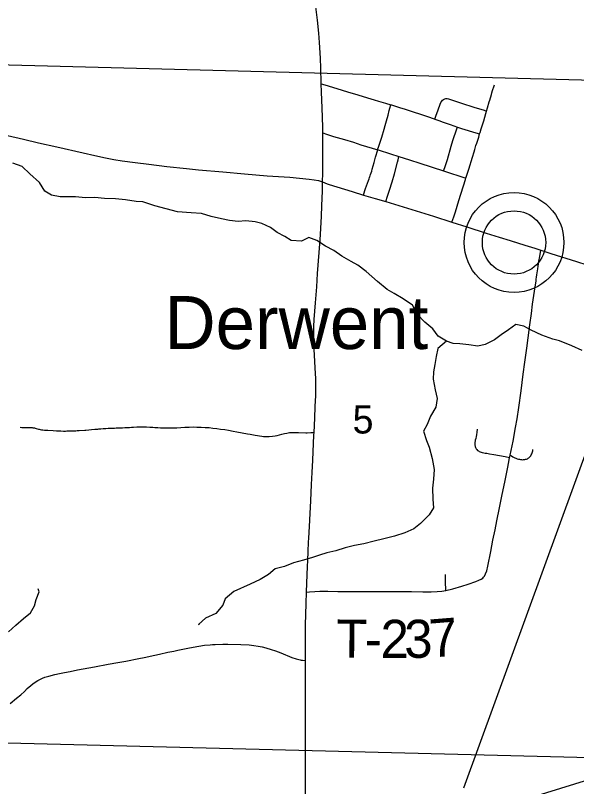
# Model space of a CAD drawing. Extents: x 0 to 34, y 0 to 22.
# Drawn here: x 28.206 to 29.042, y 19.567 to 20.718 of the extents above; entities that cross this region are included whole.
import ezdxf

# ---------------------------------------------------------------- set-up
doc = ezdxf.new("R2010")
doc.units = 0
for name, color, linetype in [('GM_X_Corporation', 7, 'Continuous'), ('GM_X_Minor_River', 7, 'Continuous'), ('GM_X_Rail_Line', 7, 'Continuous'), ('GM_X_Section_Text', 7, 'Continuous'), ('GM_X_State_Route', 7, 'Continuous'), ('GM_X_Township_Road', 7, 'Continuous'), ('GM_X_Township_Road_Text', 7, 'Continuous'), ('GM_X_Unincorporated', 7, 'Continuous'), ('GM_X_Unincorporated_Location', 7, 'Continuous'), ('GM_X_Unincorporated_Text', 7, 'Continuous')]:
    doc.layers.add(name, color=color, linetype=linetype)

msp = doc.modelspace()

# ---------------------------------------------------------------- linework, layer by layer
at = {"layer": 'GM_X_Corporation'}
for points in [[(29.1717, 20.9), (28.1474, 20.9), (28.1412, 20.646), (28.1583, 20.645), (29.1631, 20.6187)], [(28.1583, 20.645), (29.1631, 20.6187), (29.1414, 19.6082), (28.1343, 19.6338)]]:
    msp.add_lwpolyline(points, close=True, dxfattribs=at)
at = {"layer": 'GM_X_Minor_River'}
for points in [[(29.0505, 20.2181), (29.0349, 20.2248), (29.0167, 20.2322), (29.0065, 20.2347), (28.9902, 20.241), (28.9742, 20.248), (28.9636, 20.254), (28.9515, 20.2565), (28.9406, 20.2488), (28.9297, 20.2415), (28.9199, 20.2338), (28.906, 20.2268), (28.895, 20.2244), (28.8814, 20.2262), (28.8682, 20.228), (28.8583, 20.2282), (28.8481, 20.2319), (28.8356, 20.2394), (28.8279, 20.2503), (28.8157, 20.26), (28.8046, 20.272), (28.7977, 20.2856), (28.7837, 20.2949), (28.7704, 20.3027), (28.7597, 20.309), (28.7452, 20.321), (28.7285, 20.3356), (28.7159, 20.3454), (28.706, 20.3506), (28.6924, 20.3584), (28.6802, 20.367), (28.6677, 20.3733), (28.6547, 20.3818), (28.643, 20.3866), (28.6321, 20.3812), (28.6169, 20.3818), (28.6074, 20.3878), (28.5957, 20.3937), (28.5861, 20.4012), (28.5729, 20.4075), (28.563, 20.4097), (28.549, 20.4111), (28.5377, 20.4102), (28.5248, 20.4116), (28.5127, 20.4145), (28.4975, 20.4177), (28.4831, 20.4221), (28.4676, 20.4231), (28.4472, 20.4248), (28.4135, 20.4335), (28.3957, 20.4394), (28.3854, 20.44), (28.3699, 20.4425), (28.3548, 20.4439), (28.3385, 20.4448), (28.3241, 20.4462), (28.3102, 20.4457), (28.2954, 20.447), (28.2833, 20.4469), (28.2724, 20.4472), (28.2595, 20.4497), (28.2496, 20.4553), (28.2415, 20.4685), (28.2271, 20.4816), (28.2156, 20.4921), (28.202, 20.4972)], [(28.8481, 20.2319), (28.8353, 20.2208), (28.8328, 20.209), (28.8306, 20.1969), (28.8288, 20.1859), (28.8282, 20.1752), (28.8314, 20.159), (28.8345, 20.1461), (28.8323, 20.1336), (28.8245, 20.1199), (28.8193, 20.1073), (28.8141, 20.0978), (28.8184, 20.0838), (28.8223, 20.0736), (28.827, 20.0566), (28.8297, 20.0403), (28.8287, 20.0259), (28.8273, 20.0127), (28.8279, 19.9964), (28.8287, 19.9831), (28.8224, 19.9728), (28.8093, 19.9598), (28.7995, 19.9517), (28.786, 19.9459), (28.7705, 19.9412), (28.755, 19.9369), (28.7403, 19.9333), (28.7249, 19.9297), (28.7109, 19.9269), (28.697, 19.9234), (28.6834, 19.9191), (28.6698, 19.9159), (28.6589, 19.9124), (28.6487, 19.9092), (28.6351, 19.9053), (28.62, 19.901), (28.6068, 19.8959), (28.5929, 19.892), (28.5831, 19.8839), (28.5703, 19.8762), (28.5557, 19.8692), (28.5312, 19.8584), (28.5184, 19.8476), (28.5147, 19.8381), (28.5046, 19.8255), (28.4892, 19.8189), (28.4787, 19.8093), (28.4798, 19.8097)], [(28.1953, 19.7984), (28.2062, 19.808), (28.2178, 19.8183), (28.2279, 19.8267), (28.2339, 19.837), (28.2368, 19.8465), (28.2409, 19.858), (28.2397, 19.8625)]]:
    msp.add_lwpolyline(points, dxfattribs=at)
at = {"layer": 'GM_X_Rail_Line'}
for points in [[(28.8741, 19.5654), (29.0627, 20.0841), (29.0894, 20.1621), (29.1142, 20.2409), (29.1356, 20.3363), (29.1474, 20.4062), (29.1551, 20.4639), (29.161, 20.4964)], [(28.8515, 19.5134), (29.4007, 19.6833), (29.491, 19.707), (29.5813, 19.7244), (29.9149, 19.7778), (30.0206, 19.7932), (30.1151, 19.8044), (30.1859, 19.8065), (30.2475, 19.8096), (30.2867, 19.817), (30.3167, 19.8284)]]:
    msp.add_lwpolyline(points, dxfattribs=at)
at = {"layer": 'GM_X_State_Route'}
for points in [[(28.6394, 19.8575), (28.6398, 19.8711), (28.6409, 19.8959), (28.6414, 19.9046), (28.6422, 19.9182), (28.6427, 19.9318), (28.643, 19.938), (28.6438, 19.9553), (28.6448, 19.975), (28.6458, 19.9939), (28.6469, 20.0179), (28.6478, 20.0359), (28.6488, 20.0545), (28.6506, 20.0917), (28.6508, 20.0956), (28.6517, 20.1171), (28.6526, 20.1345), (28.6532, 20.1506), (28.6534, 20.1624), (28.6533, 20.1754), (28.6526, 20.1921), (28.6515, 20.2107), (28.6505, 20.2274), (28.6502, 20.2393), (28.6503, 20.2536), (28.6508, 20.2642), (28.6529, 20.289), (28.6548, 20.3131), (28.6561, 20.3329), (28.6598, 20.383), (28.6609, 20.3997), (28.6617, 20.4183), (28.6623, 20.4338), (28.6633, 20.4561), (28.6636, 20.4694), (28.664, 20.4822), (28.664, 20.4939), (28.6638, 20.5281), (28.6637, 20.5427), (28.6637, 20.5504), (28.6634, 20.5659), (28.6629, 20.5795), (28.6621, 20.6037), (28.6616, 20.6157), (28.6616, 20.6173), (28.6609, 20.639), (28.6602, 20.6539), (28.6587, 20.6775), (28.6577, 20.6911), (28.6557, 20.7108), (28.6534, 20.7305)], [(28.194, 20.5387), (28.2175, 20.533), (28.2399, 20.5277), (28.2672, 20.5216), (28.3066, 20.5126), (28.3241, 20.5087), (28.3399, 20.5055), (28.3521, 20.503), (28.365, 20.501), (28.384, 20.4983), (28.4043, 20.4956), (28.4314, 20.4923), (28.4605, 20.4893), (28.4784, 20.4875), (28.5149, 20.4842), (28.5471, 20.4813), (28.5811, 20.4786), (28.6146, 20.4763), (28.6437, 20.4735), (28.6511, 20.4724), (28.6573, 20.4713), (28.6636, 20.4694)], [(28.6636, 20.4694), (28.6666, 20.4682), (28.6704, 20.4667), (28.6734, 20.4656), (28.7074, 20.4551), (28.7247, 20.4498), (28.7419, 20.4447), (28.7578, 20.4399), (28.7966, 20.4282), (28.8286, 20.4182), (28.8562, 20.4093), (28.8783, 20.4022), (28.9073, 20.3931), (28.9269, 20.3869), (28.9429, 20.3818), (28.9648, 20.3749), (28.9796, 20.3703), (28.9886, 20.3674), (29.0039, 20.3626), (29.0418, 20.3506), (29.0726, 20.3408)], [(28.6379, 19.7557), (28.638, 19.7762), (28.6381, 19.8084), (28.6389, 19.8405), (28.6394, 19.8575)], [(28.606, 19.2817), (28.6063, 19.2837), (28.6157, 19.3357), (28.6257, 19.3939), (28.6312, 19.4269), (28.6332, 19.4423), (28.6349, 19.4583), (28.6361, 19.4726), (28.637, 19.4918), (28.6376, 19.5135), (28.6378, 19.5371), (28.6379, 19.5812), (28.638, 19.6334), (28.6379, 19.6607), (28.6381, 19.6999), (28.638, 19.7191), (28.6378, 19.7415), (28.6379, 19.7557)]]:
    msp.add_lwpolyline(points, dxfattribs=at)
at = {"layer": 'GM_X_Township_Road'}
msp.add_line((28.8438, 20.4857), (28.877, 20.4747), dxfattribs=at)
for points in [[(28.6616, 20.6157), (28.6669, 20.614), (28.6847, 20.6087), (28.7006, 20.6039), (28.7162, 20.5992), (28.7304, 20.5949), (28.7404, 20.5919), (28.7469, 20.59), (28.7575, 20.5869), (28.7651, 20.5845)], [(28.9079, 20.5751), (28.9092, 20.5796), (28.9119, 20.5889), (28.9126, 20.5912), (28.9136, 20.5947), (28.9141, 20.5964), (28.9151, 20.5998), (28.9157, 20.6021), (28.9168, 20.6056), (28.9193, 20.6125), (28.9199, 20.6142)], [(28.831, 20.563), (28.8325, 20.5674), (28.8357, 20.5769), (28.8385, 20.5851), (28.8397, 20.5879), (28.841, 20.59), (28.8423, 20.5914), (28.8438, 20.5925), (28.8455, 20.5933), (28.8473, 20.5937), (28.8491, 20.5937), (28.8514, 20.5933), (28.8704, 20.5869), (28.8887, 20.581), (28.9041, 20.5763), (28.9079, 20.5751)], [(28.7456, 20.5173), (28.746, 20.5188), (28.7466, 20.521), (28.7507, 20.5331), (28.7516, 20.536), (28.7554, 20.5478), (28.757, 20.5537), (28.7589, 20.5605), (28.761, 20.5687), (28.7627, 20.5758), (28.7637, 20.5793), (28.7651, 20.5845)], [(28.7651, 20.5845), (28.7664, 20.5841), (28.7782, 20.5805), (28.7865, 20.5779), (28.7953, 20.5751), (28.8017, 20.5731), (28.8063, 20.5715), (28.8139, 20.5689), (28.8215, 20.5663), (28.8285, 20.5639), (28.831, 20.563)], [(28.8976, 20.541), (28.8983, 20.5429), (28.9001, 20.5487), (28.9036, 20.5606), (28.9069, 20.5715), (28.9079, 20.5751)], [(28.831, 20.563), (28.8367, 20.5609), (28.8431, 20.5586), (28.8536, 20.555), (28.8589, 20.5532), (28.8648, 20.5512)], [(28.6637, 20.5427), (28.6694, 20.5406), (28.6723, 20.5396), (28.68, 20.5373), (28.6963, 20.5324), (28.7095, 20.5285), (28.7207, 20.5249), (28.7456, 20.5173)], [(28.8438, 20.4857), (28.8455, 20.4906), (28.8496, 20.5029), (28.8553, 20.5226), (28.8577, 20.5309), (28.8638, 20.5485), (28.8648, 20.5512)], [(28.8648, 20.5512), (28.8706, 20.5492), (28.8807, 20.5459), (28.8884, 20.5437), (28.8976, 20.541)], [(28.877, 20.4747), (28.8815, 20.4882), (28.887, 20.5063), (28.8892, 20.5144), (28.8902, 20.5178), (28.8921, 20.5235), (28.8932, 20.527), (28.8953, 20.5332), (28.8962, 20.5361), (28.8976, 20.541)], [(28.7247, 20.4498), (28.7267, 20.4564), (28.7276, 20.4594), (28.7319, 20.4717), (28.7328, 20.474), (28.7334, 20.4757), (28.734, 20.4774), (28.7344, 20.4786), (28.735, 20.4804), (28.7367, 20.4856), (28.7375, 20.4886), (28.7403, 20.4981), (28.7426, 20.5064), (28.7456, 20.5173)], [(28.7456, 20.5173), (28.7462, 20.5171), (28.7645, 20.5112), (28.7771, 20.5072)], [(28.7578, 20.4399), (28.7603, 20.4481), (28.7631, 20.457), (28.767, 20.4694), (28.7705, 20.4814), (28.7752, 20.4988), (28.776, 20.5024), (28.7771, 20.5072)], [(28.7771, 20.5072), (28.7929, 20.5022), (28.8083, 20.4975), (28.8438, 20.4857)], [(28.8562, 20.4093), (28.8589, 20.4175), (28.8614, 20.4245), (28.8666, 20.4417), (28.8764, 20.4729), (28.877, 20.4747)], [(28.9429, 20.0616), (28.9444, 20.0689), (28.9473, 20.0829), (28.9512, 20.103), (28.9535, 20.1158), (28.9561, 20.133), (28.9595, 20.1576), (28.9627, 20.1828), (28.9651, 20.2006), (28.9679, 20.2216), (28.9699, 20.237), (28.9724, 20.2561), (28.9747, 20.2733), (28.9766, 20.2868), (28.9804, 20.3127), (28.9816, 20.3212), (28.982, 20.3242), (28.9825, 20.3271), (28.983, 20.3307), (28.9835, 20.3336), (28.9839, 20.3366), (28.9843, 20.3396), (28.9849, 20.3438), (28.986, 20.3513), (28.9871, 20.3581), (28.9886, 20.3674)], [(28.2126, 20.1033), (28.2151, 20.1031), (28.2193, 20.1028), (28.2224, 20.1028), (28.2255, 20.1029), (28.2291, 20.1028), (28.2305, 20.1028), (28.2314, 20.1027), (28.2321, 20.1027), (28.2327, 20.1026), (28.2339, 20.1024), (28.2351, 20.1021), (28.2365, 20.1017), (28.24, 20.1007), (28.2412, 20.1004), (28.2423, 20.1001), (28.2444, 20.0997), (28.2455, 20.0995), (28.2466, 20.0994), (28.249, 20.0992), (28.254, 20.0989), (28.262, 20.0985), (28.2669, 20.0982), (28.2711, 20.0979), (28.2734, 20.0979), (28.2773, 20.0978), (28.2782, 20.0978), (28.2801, 20.0978), (28.2821, 20.0979), (28.2849, 20.0979), (28.2872, 20.098), (28.29, 20.0981), (28.2928, 20.0982), (28.2956, 20.0983), (28.2977, 20.0984), (28.3005, 20.0986), (28.309, 20.0991), (28.3108, 20.0992), (28.3149, 20.0996), (28.3191, 20.0999), (28.3238, 20.1004), (28.3287, 20.1008), (28.3299, 20.1009), (28.3329, 20.1012), (28.3365, 20.1015), (28.3384, 20.1016), (28.3404, 20.1018), (28.3437, 20.102), (28.346, 20.102), (28.3484, 20.1022), (28.35, 20.1022), (28.3512, 20.1022), (28.3523, 20.1023), (28.3535, 20.1023), (28.3558, 20.1024), (28.3587, 20.1025), (28.3622, 20.1025), (28.3636, 20.1026), (28.3653, 20.1026), (28.3688, 20.1028), (28.3724, 20.103), (28.3759, 20.1032), (28.3789, 20.1034), (28.3819, 20.1036), (28.3865, 20.1038), (28.3887, 20.1039), (28.3902, 20.1039), (28.3911, 20.1039), (28.3934, 20.1039), (28.3957, 20.1039), (28.3981, 20.1039), (28.4011, 20.1038), (28.406, 20.1036), (28.4103, 20.1034), (28.4134, 20.1032), (28.4177, 20.1029), (28.4221, 20.1027), (28.4301, 20.1024), (28.4344, 20.1024), (28.44, 20.1024), (28.4461, 20.1027), (28.4522, 20.1032), (28.4584, 20.1035), (28.4602, 20.1035), (28.4646, 20.1037), (28.4707, 20.1038), (28.4763, 20.1037), (28.4825, 20.1035), (28.4887, 20.1032), (28.4942, 20.1028), (28.4998, 20.1023), (28.5059, 20.1015), (28.5114, 20.1008), (28.5176, 20.0999), (28.5231, 20.099), (28.5304, 20.0977), (28.5359, 20.0968), (28.5438, 20.0952), (28.5516, 20.0937), (28.5553, 20.093), (28.5607, 20.092), (28.5631, 20.0915), (28.5729, 20.09), (28.5753, 20.0897), (28.5785, 20.0895), (28.5814, 20.0895), (28.584, 20.0895), (28.589, 20.09), (28.5926, 20.0906), (28.5957, 20.0912), (28.6029, 20.093), (28.6065, 20.0939), (28.6101, 20.0947), (28.6143, 20.0954), (28.6168, 20.0956), (28.6198, 20.0958), (28.6216, 20.0957), (28.6252, 20.0957), (28.6275, 20.0955), (28.6383, 20.0952), (28.6406, 20.0952), (28.6458, 20.0954), (28.6508, 20.0956)], [(28.8939, 20.1005), (28.8933, 20.0959), (28.8928, 20.0919), (28.8923, 20.0896), (28.8917, 20.0867), (28.8911, 20.084), (28.8904, 20.0797), (28.8904, 20.0772), (28.8908, 20.0748), (28.8914, 20.073), (28.8926, 20.0712), (28.8934, 20.0701), (28.8945, 20.0689), (28.8957, 20.0681), (28.8969, 20.0673), (28.8986, 20.0666), (28.9015, 20.0657), (28.9039, 20.0653), (28.9058, 20.065), (28.9082, 20.0646), (28.9125, 20.064), (28.9187, 20.0627), (28.9271, 20.0611), (28.9356, 20.0596), (28.9423, 20.0585)], [(28.9423, 20.0585), (28.9426, 20.0598), (28.9429, 20.0616)], [(28.9429, 20.0616), (28.9449, 20.0606), (28.9469, 20.0595), (28.9489, 20.0584), (28.9501, 20.0579), (28.9514, 20.0574), (28.9536, 20.0565), (28.9554, 20.056), (28.9569, 20.0556), (28.9585, 20.0553), (28.96, 20.0551), (28.9616, 20.055), (28.9631, 20.0551), (28.9647, 20.0553), (28.9661, 20.0556), (28.9673, 20.0559), (28.9687, 20.0564), (28.9698, 20.0571), (28.9708, 20.0577), (28.972, 20.0587), (28.9733, 20.0601), (28.974, 20.061), (28.9746, 20.0621), (28.9753, 20.0637), (28.976, 20.0655), (28.9767, 20.0683), (28.9771, 20.0704)], [(28.8471, 19.8601), (28.8574, 19.8625), (28.8712, 19.8664), (28.8806, 19.8696), (28.8917, 19.8734), (28.8965, 19.8751), (28.8999, 19.8768), (28.9021, 19.8783), (28.9035, 19.8797), (28.9046, 19.8813), (28.9065, 19.8847), (28.9082, 19.8894), (28.9099, 19.8961), (28.9141, 19.918), (28.9173, 19.9351), (28.9205, 19.9503), (28.9231, 19.9637), (28.9271, 19.9831), (28.9308, 20.0007), (28.9355, 20.0239), (28.939, 20.0415), (28.9412, 20.0519), (28.9423, 20.0585)], [(28.8471, 19.8601), (28.847, 19.8637), (28.8469, 19.8692), (28.8469, 19.8754), (28.8469, 19.882), (28.8469, 19.8837)], [(28.6379, 19.7557), (28.638, 19.7762), (28.6381, 19.8084), (28.6389, 19.8405), (28.6394, 19.8575)], [(28.6394, 19.8575), (28.644, 19.8578), (28.6518, 19.8582), (28.6592, 19.8587), (28.6715, 19.8587), (28.6864, 19.8585), (28.6958, 19.8585), (28.7175, 19.8585), (28.7336, 19.8584), (28.7466, 19.8585), (28.7547, 19.8586), (28.7739, 19.8584), (28.7881, 19.8583), (28.7962, 19.8582), (28.8129, 19.858), (28.8254, 19.8581), (28.8341, 19.8584), (28.841, 19.859), (28.8471, 19.8601)], [(28.1977, 19.6914), (28.2075, 19.6992), (28.2136, 19.7045), (28.219, 19.7095), (28.2234, 19.7139), (28.2286, 19.7183), (28.2316, 19.7205), (28.2366, 19.7241), (28.2393, 19.7257), (28.242, 19.7272), (28.2459, 19.7291), (28.2494, 19.7305), (28.2553, 19.7324), (28.2643, 19.7346), (28.2716, 19.7361), (28.2789, 19.7375), (28.2874, 19.7392), (28.2984, 19.7414), (28.3234, 19.7461), (28.3441, 19.75), (28.3581, 19.7523), (28.3643, 19.7533), (28.3704, 19.7544), (28.3898, 19.7584), (28.3976, 19.7602), (28.4133, 19.7637), (28.4203, 19.7652), (28.4328, 19.7679), (28.4418, 19.7695), (28.4479, 19.7709), (28.4527, 19.7719), (28.4551, 19.7725), (28.4624, 19.7739), (28.4708, 19.7755), (28.4792, 19.7769), (28.4876, 19.7782), (28.4961, 19.779), (28.4995, 19.7792), (28.5035, 19.7793), (28.515, 19.7798), (28.5224, 19.78), (28.5416, 19.7795), (28.554, 19.7788), (28.5608, 19.778), (28.5676, 19.7769), (28.5736, 19.7757), (28.5787, 19.7745), (28.5868, 19.7721), (28.5933, 19.7699), (28.6014, 19.7668), (28.6175, 19.7601), (28.6239, 19.7579), (28.6261, 19.7573), (28.6281, 19.7568), (28.63, 19.7564), (28.6318, 19.7562), (28.6336, 19.756), (28.6379, 19.7557)]]:
    msp.add_lwpolyline(points, dxfattribs=at)
at = {"layer": 'GM_X_Unincorporated'}
for radius in [0.0744, 0.0472]:
    msp.add_circle((28.9488, 20.379), radius, dxfattribs=at)
at = {"layer": 'GM_X_Unincorporated_Location'}
msp.add_line((28.9488, 20.379), (28.9488, 20.379), dxfattribs=at)

# ---------------------------------------------------------------- texts
at = {"layer": 'GM_X_Section_Text'}
msp.add_text('5', height=0.0419, rotation=0, dxfattribs=at).set_placement((28.7082, 20.0941))
at = {"layer": 'GM_X_Township_Road_Text'}
for s, rotation, p in [('7', 4.6485, (28.825, 19.7598)), ('T', 359.6743, (28.6838, 19.7599)), ('2', 359.8255, (28.7498, 19.7595)), ('3', 0.3059, (28.7853, 19.7594)), ('-', 359.7017, (28.7263, 19.7596))]:
    msp.add_text(s, height=0.0568, rotation=rotation, dxfattribs=at).set_placement(p)
at = {"layer": 'GM_X_Unincorporated_Text'}
msp.add_text('Derwent', height=0.07898, rotation=0, dxfattribs=at).set_placement((28.4278, 20.2201))

doc.saveas('drawing.dxf')
